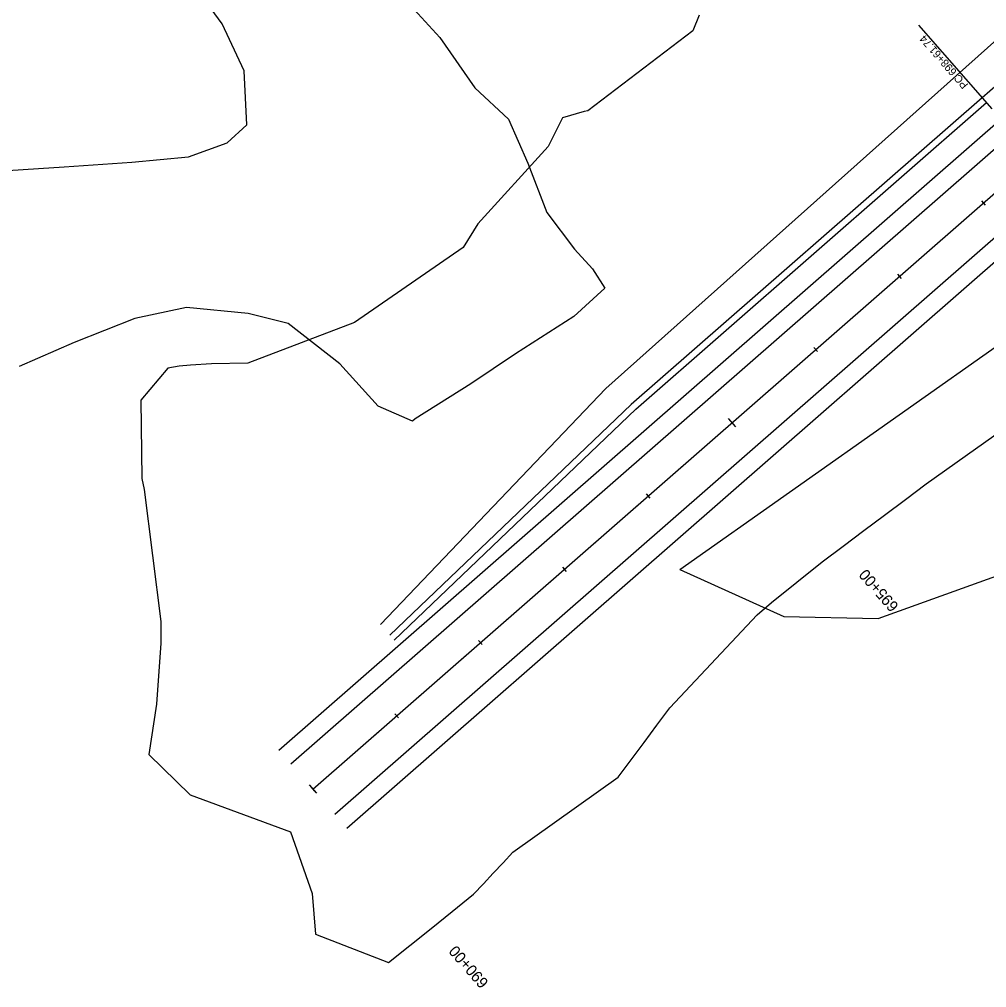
# Model space of a CAD drawing. Extents: x 1300404 to 1323571, y 234004 to 252077.
# Drawn here: x 1308164 to 1309033, y 238758 to 239629 of the extents above; entities that cross this region are included whole.
import ezdxf

# ---------------------------------------------------------------- set-up
doc = ezdxf.new("R2010")
doc.units = 0
for name, color, linetype in [('R_Flooplain', 7, 'Continuous'), ('R_Horz Alg Station Annot', 7, 'Continuous'), ('R_Lane Edge', 7, 'Continuous'), ('R_Shoulder', 7, 'Continuous'), ('S_EDGE_PAVEMENT_ANNOT', 7, 'Continuous'), ('S_ELECTRIC_UTILITIES_ANNOT', 7, 'Continuous'), ('S_LANDSCAPING_ANNOT', 7, 'Continuous'), ('S_POOL', 7, 'Continuous'), ('S_SANITARY_SEWER_ANNOT', 7, 'Continuous'), ('S_SIGN', 7, 'Continuous'), ('S_UTL_PT_SYM', 7, 'Continuous')]:
    doc.layers.add(name, color=color, linetype=linetype)

msp = doc.modelspace()

# ---------------------------------------------------------------- linework, layer by layer
at = {"layer": 'R_Flooplain'}
for p, q in [((1308346.19, 239624.41), (1308328.08, 239649.52)), ((1308502.57, 239655.25), (1308541.56, 239612.15)), ((1308365.87, 239582.29), (1308346.19, 239624.41)), ((1308541.56, 239612.15), (1308573.18, 239567)), ((1308368.29, 239533.77), (1308365.87, 239582.29)), ((1308573.18, 239567), (1308603.24, 239538.87)), ((1308603.24, 239538.87), (1308620.62, 239499.29)), ((1308350.55, 239517.73), (1308368.29, 239533.77)), ((1308316.04, 239504.95), (1308350.55, 239517.73)), ((1308265, 239500.27), (1308316.04, 239504.95)), ((1308121.76, 239490.54), (1308204.3, 239496.06)), ((1308204.3, 239496.06), (1308265, 239500.27)), ((1308620.62, 239499.29), (1308637.76, 239454.87)), ((1308637.76, 239454.87), (1308662.75, 239422.16)), ((1308662.75, 239422.16), (1308678.8, 239404.41)), ((1308678.8, 239404.41), (1308690.03, 239386.91)), ((1308690.03, 239386.91), (1308662.16, 239361.7)), ((1308757.29, 239134.3), (1309093.32, 239371.43)), ((1308314.14, 239369.55), (1308267.68, 239359.79)), ((1308369.53, 239364.34), (1308314.14, 239369.55)), ((1308405.37, 239355.28), (1308369.53, 239364.34)), ((1308267.68, 239359.79), (1308213.38, 239338.33)), ((1308451.95, 239319.05), (1308405.37, 239355.28)), ((1308662.16, 239361.7), (1308609.67, 239328.05)), ((1308213.38, 239338.33), (1308163.91, 239316.63)), ((1308609.67, 239328.05), (1308569.61, 239301.03)), ((1308486.35, 239281.03), (1308451.95, 239319.05)), ((1308569.61, 239301.03), (1308519.66, 239269.67)), ((1308517.13, 239267.38), (1308486.35, 239281.03)), ((1308519.66, 239269.67), (1308517.13, 239267.38)), ((1308757.29, 239134.3), (1308850.76, 239092.09)), ((1308935.35, 239090.24), (1309053.6, 239132.68)), ((1308850.76, 239092.09), (1308935.35, 239090.24))]:
    msp.add_line(p, q, dxfattribs=at)
at = {"layer": 'R_Lane Edge'}
for p, q in [((1308717.71, 239278.28), (1309032.84, 239553.84)), ((1308500.81, 239070.58), (1308717.71, 239278.28))]:
    msp.add_line(p, q, dxfattribs=at)
at = {"layer": 'R_Shoulder'}
for p, q in [((1308713.67, 239282.72), (1309028.89, 239558.35)), ((1308496.86, 239075.1), (1308713.56, 239282.62))]:
    msp.add_line(p, q, dxfattribs=at)
msp.add_arc((1305266.27, 243861.41), 5716.08, 311.16667, 314.02346, dxfattribs=at)
at = {"layer": 'S_EDGE_PAVEMENT_ANNOT'}
msp.add_lwpolyline([(1309037.78, 239548.19), (1308971.95, 239623.47)], dxfattribs=at)
at = {"layer": 'S_ELECTRIC_UTILITIES_ANNOT'}
for points in [[(1309161.24, 239746.22), (1309174.84, 239731.08), (1309163.84, 239720.33), (1309126.38, 239686.18), (1309041.87, 239610.58), (1308690.69, 239296.76), (1308488.36, 239084.81)], [(1308774.64, 239632.28), (1308768.84, 239618.23), (1308674.56, 239546.48), (1308671.44, 239545.82), (1308651.79, 239540.06), (1308638.96, 239514.4), (1308575.75, 239444.78), (1308562.79, 239423.6), (1308465.14, 239356.04), (1308369.19, 239319.48), (1308336.7, 239318.92), (1308317.83, 239317.78), (1308307.43, 239316.97), (1308297.26, 239315.04), (1308273.27, 239286.31), (1308274.18, 239216.03), (1308276.04, 239206.06), (1308291.24, 239087.38), (1308291.07, 239068.07), (1308287.24, 239013.23), (1308280.27, 238967.85), (1308317.57, 238931.84), (1308407.52, 238898.52), (1308426.94, 238843.02), (1308430.16, 238806.53), (1308495.71, 238781.01), (1308514.77, 238796.34), (1308533.82, 238811.67), (1308552.88, 238827), (1308571.94, 238842.33), (1308580.81, 238851.79), (1308589.68, 238861.25), (1308598.55, 238870.71), (1308607.41, 238880.17), (1308701.84, 238947.53), (1308713.48, 238963.09), (1308725.11, 238978.65), (1308736.75, 238994.21), (1308748.38, 239009.77), (1308826.6, 239093.41), (1308839.73, 239104.68), (1308885, 239141.21), (1308904, 239155.19), (1308922.62, 239169.16), (1308941.24, 239183.13), (1308959.86, 239197.1), (1308978.49, 239211.07), (1309067.29, 239274.12)]]:
    msp.add_lwpolyline(points, dxfattribs=at)
at = {"layer": 'S_LANDSCAPING_ANNOT'}
for p, q in [((1308463.14, 238968.01), (1312793.8, 242754.77)), ((1308427.57, 238936.91), (1312398.96, 242409.52))]:
    msp.add_line(p, q, dxfattribs=at)
at = {"layer": 'S_POOL'}
for p, q in [((1308396.96, 238971.92), (1312368.36, 242444.53)), ((1308407.83, 238959.5), (1312379.22, 242432.11)), ((1308447.32, 238914.33), (1312418.71, 242386.94)), ((1308458.18, 238901.91), (1312429.57, 242374.52))]:
    msp.add_line(p, q, dxfattribs=at)
at = {"layer": 'S_SANITARY_SEWER_ANNOT'}
for points in [[(1308800.68, 239269.8), (1308807.26, 239262.27)], [(1308424.28, 238940.68), (1308430.86, 238933.15)], [(1308425.92, 238938.79), (1308429.22, 238935.03)]]:
    msp.add_lwpolyline(points, dxfattribs=at)
at = {"layer": 'S_SIGN'}
for points in [[(1309028.16, 239465.39), (1309031.45, 239461.63)], [(1308952.88, 239399.57), (1308956.17, 239395.8)], [(1308877.6, 239333.74), (1308880.89, 239329.98)], [(1308727.04, 239202.09), (1308730.33, 239198.33)], [(1308651.76, 239136.27), (1308655.06, 239132.5)], [(1308576.48, 239070.44), (1308579.78, 239066.68)], [(1308501.2, 239004.62), (1308504.5, 239000.85)]]:
    msp.add_lwpolyline(points, dxfattribs=at)

# ---------------------------------------------------------------- texts
at = {"layer": 'R_Horz Alg Station Annot'}
for s, p in [('695+00', (1308954.44, 239101.61)), ('690+00', (1308586.07, 238763.35))]:
    msp.add_text(s, height=10, rotation=131.16667, dxfattribs=at).set_placement(p)
at = {"layer": 'S_UTL_PT_SYM'}
msp.add_text('PC 698+61.74', height=7, rotation=131.16667, dxfattribs=at).set_placement((1309016.77, 239569.94))

doc.saveas('drawing.dxf')
